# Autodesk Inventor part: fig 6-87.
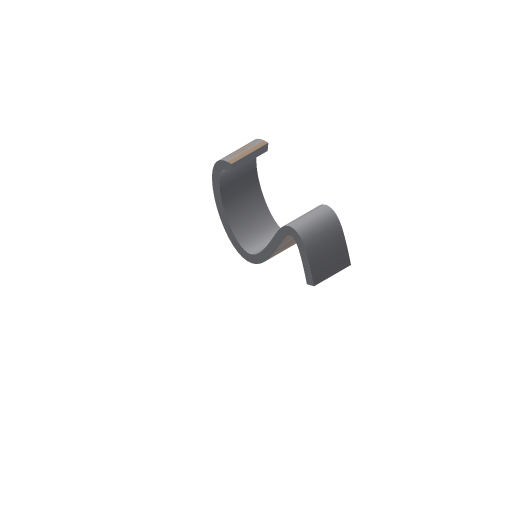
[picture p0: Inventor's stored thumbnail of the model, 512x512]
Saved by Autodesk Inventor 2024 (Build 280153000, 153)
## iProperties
Shininess: 64.0
Length Units: 11269
Angle Units: 11279
Time Units: 11290
Mass Units: 11283
Length Display Precision: 3
Angle Display Precision: 2
Compacted: True
Part Number: fig 6-87.
Document SubType Name: Modeling
Created: 2002-12
Designer: deepak
Density: 1 g/cm^3
Material: Generic
Appearance: Default
Density: 0.0
Volumn: 0.0
Area: 0.0
PropertySet Name: Model Information
Control State: 0
Master: False
Checked Out: False
Author: deepak
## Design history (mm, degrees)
sketch "Sketch1"
  geometry: 5 further points
  constraints: 5 other
extrude_surface "ExtrusionSrf1" sketch "Sketch1" dims "d0" = 20, "d1" = 0
thicken "Thicken2" dims "d6" = 4, "d7" = 4
body "Solid1"
body "Srf1"
